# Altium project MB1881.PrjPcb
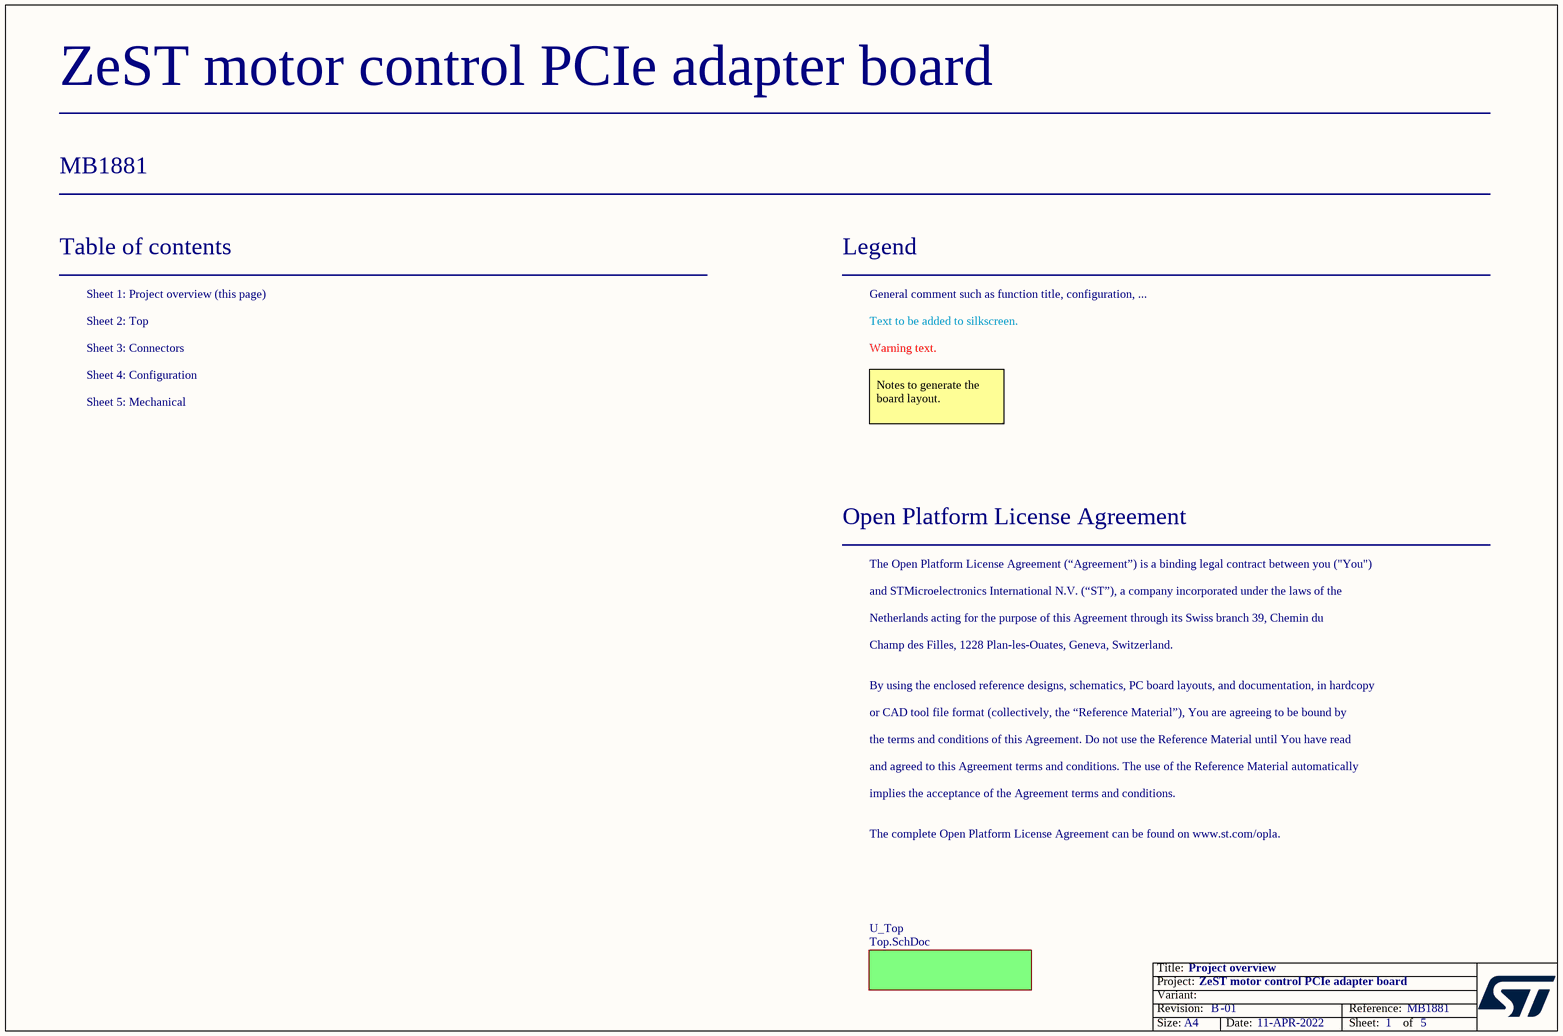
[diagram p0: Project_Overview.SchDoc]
Board_Assembly_Revision: 01; Board_Document_Date: 11-APR-2022; Board_Name: ZeST motor control PCIe adapter board; Board_PCB_Revision: B; Board_Reference: MB1881
5 sheets, 67 parts. Net scope: flat (ports and power ports of the same name join across sheets).
Board file: MB1881.PcbDoc
Sheets:
  Project_Overview.SchDoc
    U_Top = Top.SchDoc
      U_Connectors = Connectors.SchDoc
      U_Configuration = Configuration.SchDoc
      U_Mechanical = Mechanical.SchDoc

## Sheet Project_Overview.SchDoc: Project overview
size A4; Date: Not used; ApprovedBy: Not used; CheckedBy: Not used; Author: Not used; CompanyName: STMicroelectronics; DrawnBy: Not used; Engineer: Not used; Organization: Not used; Address1: Not used; Address2: Not used; Address3: Not used; Address4: Not used; DocumentNumber: Not used; Revision: Not used; SheetNumber: 1; SheetTotal: 5

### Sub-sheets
U_Top = Top.SchDoc: no entries

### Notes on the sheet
- Table of contents
- Sheet 1: Project overview (this page)
- Legend
- General comment such as function title, configuration, ...
- Sheet 2: Top
- Sheet 3: Connectors
- Sheet 4: Configuration
- Text to be added to silkscreen.
- Warning text.
- Sheet 5: Mechanical
- Notes to generate the board layout.
- Open Platform License Agreement
- The Open Platform License Agreement (“Agreement”) is a binding legal contract between you ("You")
- and STMicroelectronics International N.V. (“ST”), a company incorporated under the laws of the
- Netherlands acting for the purpose of this Agreement through its Swiss branch 39, Chemin du
- Champ des Filles, 1228 Plan-les-Ouates, Geneva, Switzerland.
- By using the enclosed reference designs, schematics, PC board layouts, and documentation, in hardcopy
- or CAD tool file format (collectively, the “Reference Material”), You are agreeing to be bound by
- the terms and conditions of this Agreement. Do not use the Reference Material until You have read
- and agreed to this Agreement terms and conditions. The use of the Reference Material automatically
- implies the acceptance of the Agreement terms and conditions.
- The complete Open Platform License Agreement can be found on www.st.com/opla.

## Sheet Top.SchDoc: Top
size A4; Date: Not used; ApprovedBy: Not used; CheckedBy: Not used; Author: Not used; CompanyName: STMicroelectronics; DrawnBy: Not used; Engineer: Not used; Organization: Not used; Address1: Not used; Address2: Not used; Address3: Not used; Address4: Not used; DocumentNumber: Not used; Revision: Not used; SheetNumber: 2; SheetTotal: 5
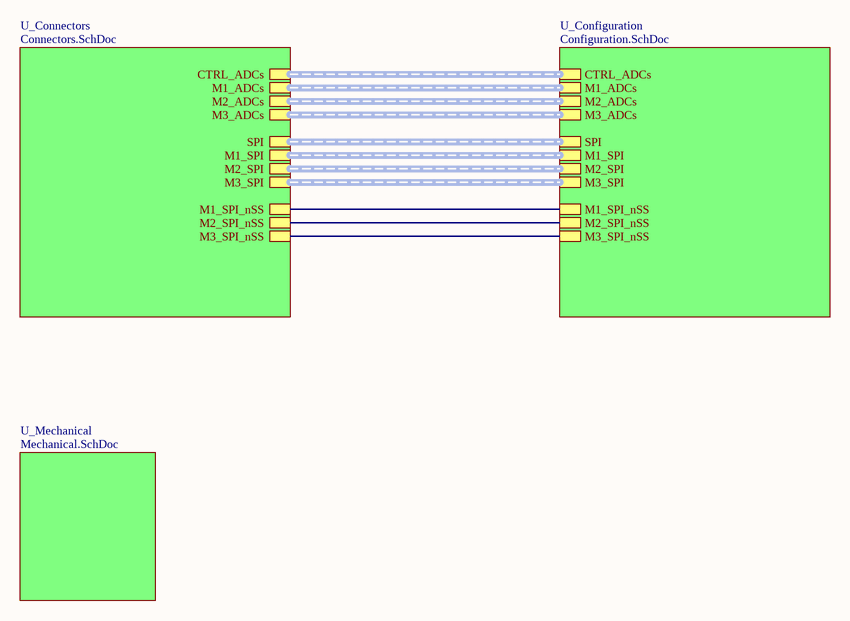
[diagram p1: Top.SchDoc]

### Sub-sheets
U_Configuration = Configuration.SchDoc: CTRL_ADCs (harness ADCs), M1_ADCs (harness ADCs), M3_ADCs (harness ADCs), M2_ADCs (harness ADCs), SPI (harness SPI), M1_SPI (harness SPI), M2_SPI (harness SPI), M3_SPI (harness SPI), M1_SPI_nSS, M3_SPI_nSS, M2_SPI_nSS
U_Connectors = Connectors.SchDoc: M3_ADCs (harness ADCs), CTRL_ADCs (harness ADCs), M1_ADCs (harness ADCs), M2_ADCs (harness ADCs), SPI (harness SPI), M1_SPI (harness SPI), M3_SPI (harness SPI), M2_SPI (harness SPI), M3_SPI_nSS, M1_SPI_nSS, M2_SPI_nSS
U_Mechanical = Mechanical.SchDoc: no entries

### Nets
(unnamed): sheet U_Connectors/M3_SPI_nSS, sheet U_Configuration/M3_SPI_nSS
(unnamed): sheet U_Connectors/M1_SPI_nSS, sheet U_Configuration/M1_SPI_nSS  [a separate net that carries the same name]
(unnamed): sheet U_Connectors/M2_SPI_nSS, sheet U_Configuration/M2_SPI_nSS  [a separate net that carries the same name]

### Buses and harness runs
harness sheet U_Configuration/CTRL_ADCs = sheet U_Connectors/CTRL_ADCs
harness sheet U_Configuration/M1_ADCs = sheet U_Connectors/M1_ADCs
harness sheet U_Configuration/M1_SPI = sheet U_Connectors/M1_SPI
harness sheet U_Configuration/M2_ADCs = sheet U_Connectors/M2_ADCs
harness sheet U_Configuration/M2_SPI = sheet U_Connectors/M2_SPI
harness sheet U_Configuration/M3_ADCs = sheet U_Connectors/M3_ADCs
harness sheet U_Configuration/M3_SPI = sheet U_Connectors/M3_SPI
harness sheet U_Configuration/SPI = sheet U_Connectors/SPI

## Sheet Connectors.SchDoc: Connectors
size A3; Date: Not used; ApprovedBy: Not used; CheckedBy: Not used; Author: Not used; CompanyName: STMicroelectronics; DrawnBy: Not used; Engineer: Not used; Organization: Not used; Address1: Not used; Address2: Not used; Address3: Not used; Address4: Not used; DocumentNumber: Not used; Revision: Not used; SheetNumber: 3; SheetTotal: 5
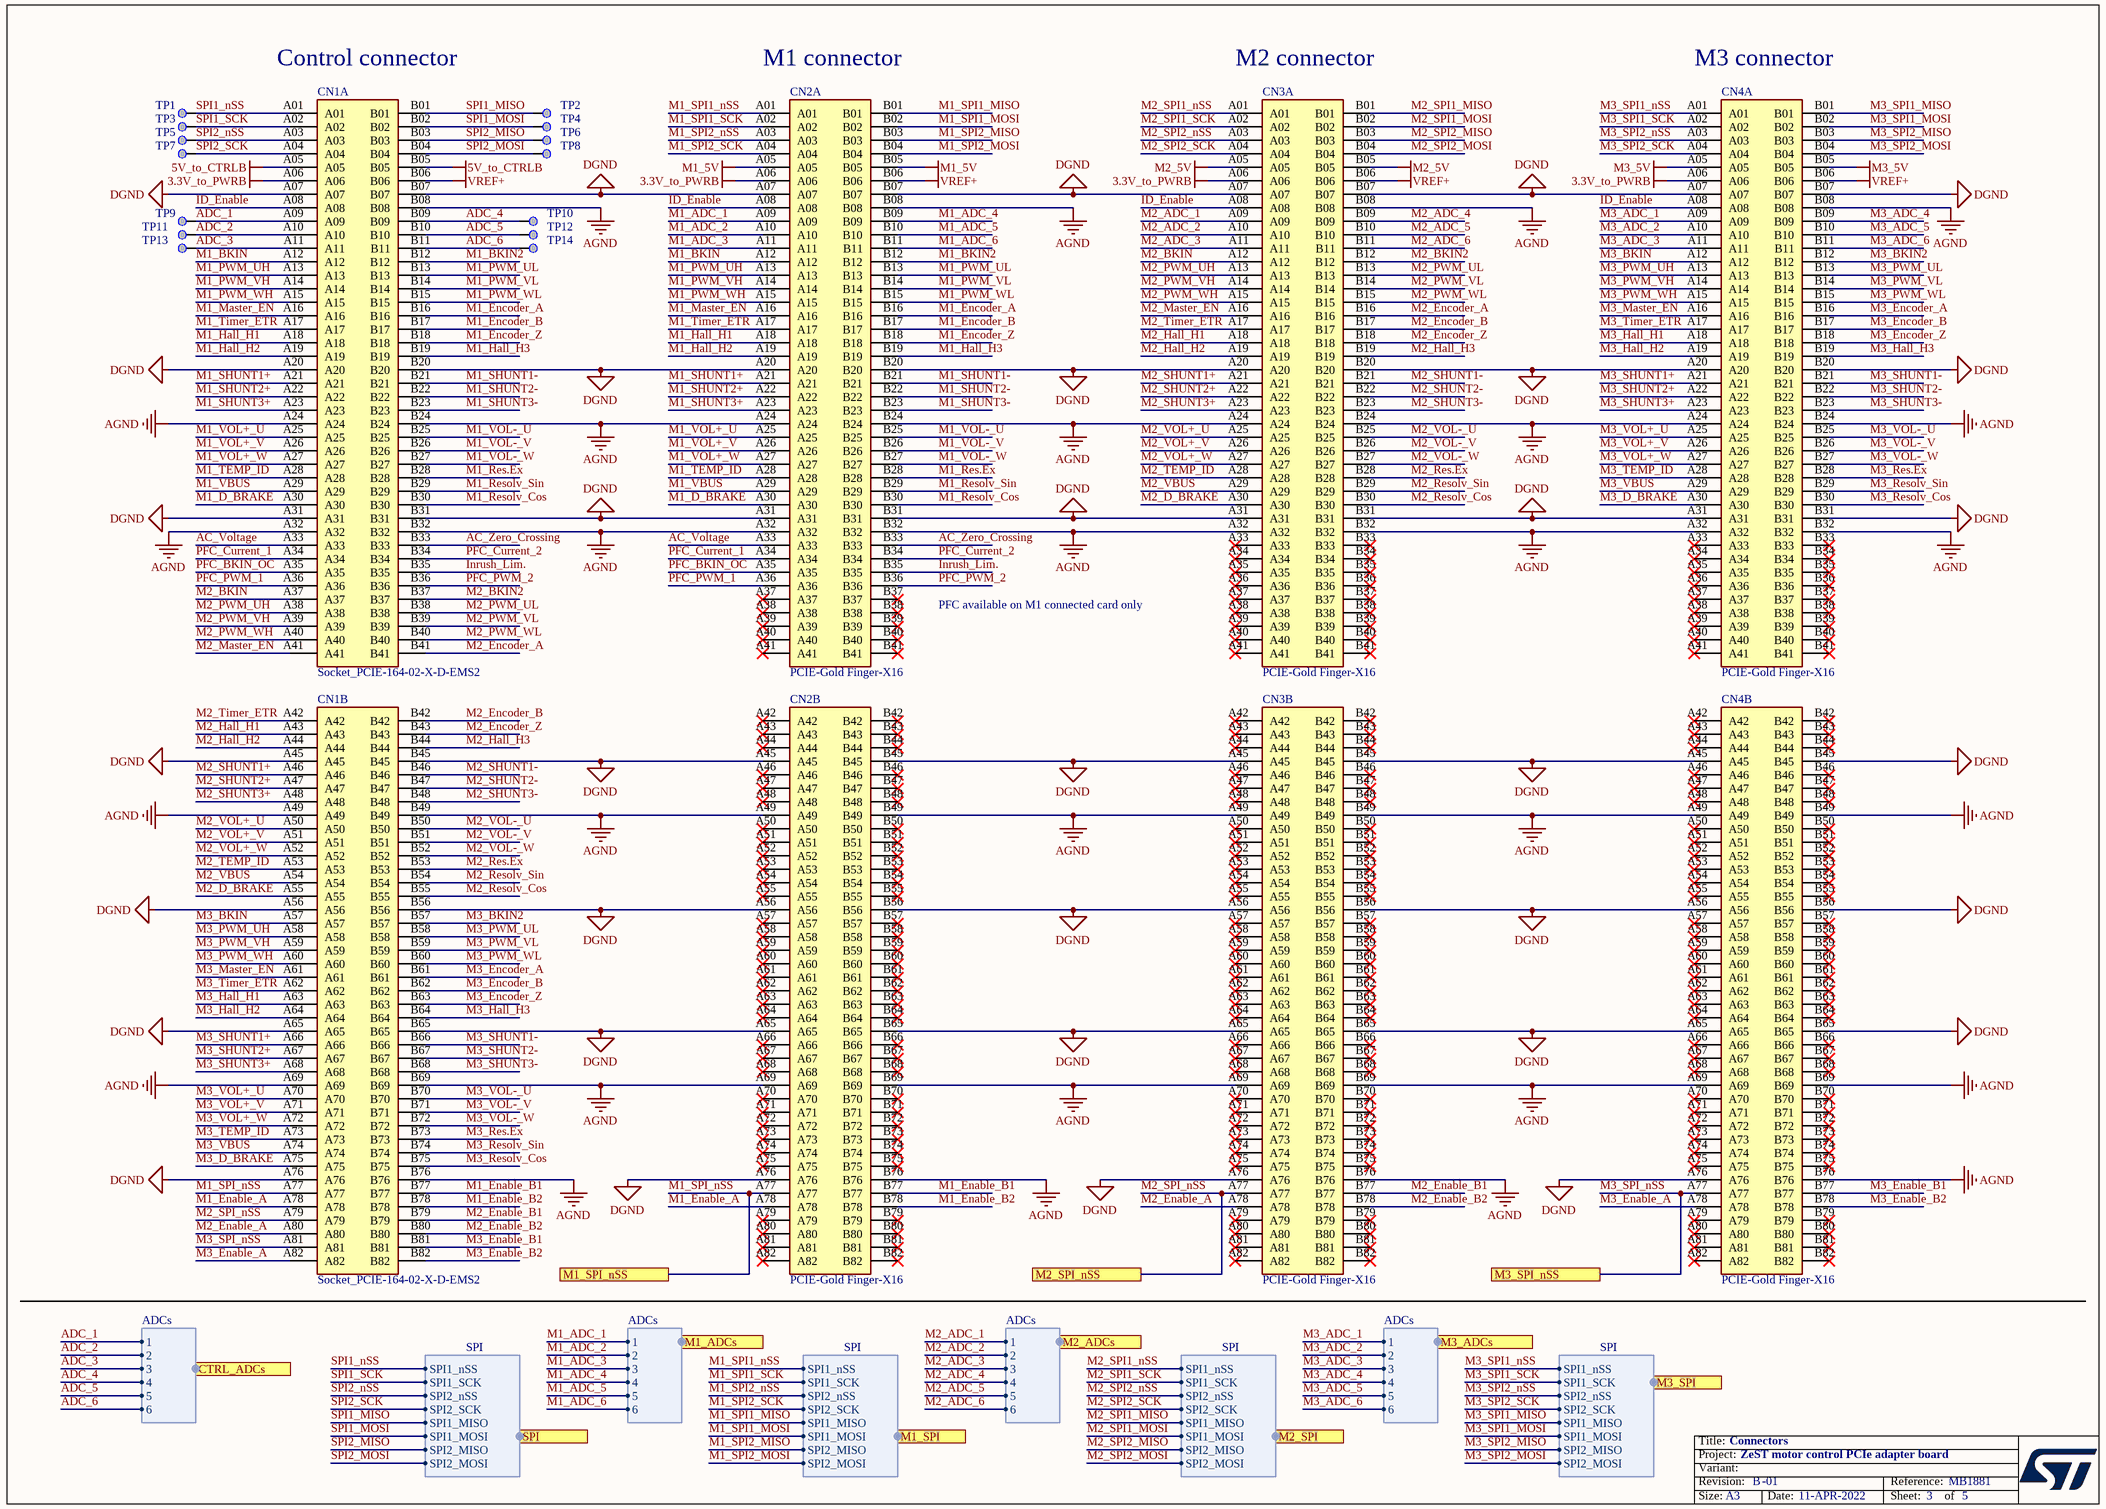
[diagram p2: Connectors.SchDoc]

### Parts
CN1  value Socket_PCIE-164-02-X-D-EMS2  [CON_SAMTEC_PCIE-164-02-X-D-EMS2]  (hidden comment: PCIE-164-02-X-D-EMS2)  (parts A,B of 2)
CN2  PCIE-Gold Finger-X16  [CON_BOARD_GOLDFINGER_PCI_EXPRESS_X16]  (parts A,B of 2)
CN3  PCIE-Gold Finger-X16  [CON_BOARD_GOLDFINGER_PCI_EXPRESS_X16]  (parts A,B of 2)
CN4  PCIE-Gold Finger-X16  [CON_BOARD_GOLDFINGER_PCI_EXPRESS_X16]  (parts A,B of 2)
TP1  Test Point  [TP_SMD_1MM]  (value not drawn)  (no BOM)
TP2  Test Point  [TP_SMD_1MM]  (value not drawn)  (no BOM)
TP3  Test Point  [TP_SMD_1MM]  (value not drawn)  (no BOM)
TP4  Test Point  [TP_SMD_1MM]  (value not drawn)  (no BOM)
TP5  Test Point  [TP_SMD_1MM]  (value not drawn)  (no BOM)
TP6  Test Point  [TP_SMD_1MM]  (value not drawn)  (no BOM)
TP7  Test Point  [TP_SMD_1MM]  (value not drawn)  (no BOM)
TP8  Test Point  [TP_SMD_1MM]  (value not drawn)  (no BOM)
TP9  Test Point  [TP_SMD_1MM]  (value not drawn)  (no BOM)
TP10  Test Point  [TP_SMD_1MM]  (value not drawn)  (no BOM)
TP11  Test Point  [TP_SMD_1MM]  (value not drawn)  (no BOM)
TP12  Test Point  [TP_SMD_1MM]  (value not drawn)  (no BOM)
TP13  Test Point  [TP_SMD_1MM]  (value not drawn)  (no BOM)
TP14  Test Point  [TP_SMD_1MM]  (value not drawn)  (no BOM)

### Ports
CTRL_ADCs (harness ADCs), M1_ADCs (harness ADCs), M1_SPI (harness SPI), M1_SPI_nSS, M2_ADCs (harness ADCs), M2_SPI (harness SPI), M2_SPI_nSS, M3_ADCs (harness ADCs), M3_SPI (harness SPI), M3_SPI_nSS, SPI (harness SPI)

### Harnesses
ADCs: 1, 2, 3, 4, 5, 6
SPI: SPI1_nSS, SPI1_SCK, SPI2_nSS, SPI2_SCK, SPI1_MISO, SPI1_MOSI, SPI2_MISO, SPI2_MOSI

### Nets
3.3V_to_PWRB: CN1.A06 CN2.A06 CN3.A06 CN4.A06
5V_to_CTRLB: CN1.A05 CN1.B05
AGND: CN1.A24 CN1.A32 CN1.A49 CN1.A69 CN1.B08 CN1.B24 CN1.B32 CN1.B49 CN1.B69 CN1.B76 CN2.A24 CN2.A32 CN2.A49 CN2.A69 CN2.B08 CN2.B24 CN2.B32 CN2.B49 CN2.B69 CN2.B76 CN3.A24 CN3.A32 CN3.A49 CN3.A69 CN3.B08 CN3.B24 CN3.B32 CN3.B49 CN3.B69 CN3.B76 CN4.A24 CN4.A32 CN4.A49 CN4.A69 CN4.B08 CN4.B24 CN4.B32 CN4.B49 CN4.B69 CN4.B76
DGND: CN1.A07 CN1.A20 CN1.A31 CN1.A45 CN1.A56 CN1.A65 CN1.A76 CN1.B07 CN1.B20 CN1.B31 CN1.B45 CN1.B56 CN1.B65 CN2.A07 CN2.A20 CN2.A31 CN2.A45 CN2.A56 CN2.A65 CN2.A76 CN2.B07 CN2.B20 CN2.B31 CN2.B45 CN2.B56 CN2.B65 CN3.A07 CN3.A20 CN3.A31 CN3.A45 CN3.A56 CN3.A65 CN3.A76 CN3.B07 CN3.B20 CN3.B31 CN3.B45 CN3.B56 CN3.B65 CN4.A07 CN4.A20 CN4.A31 CN4.A45 CN4.A56 CN4.A65 CN4.A76 CN4.B07 CN4.B20 CN4.B31 CN4.B45 CN4.B56 CN4.B65
M1_5V: CN2.A05 CN2.B05
M2_5V: CN3.A05 CN3.B05
M3_5V: CN4.A05 CN4.B05
VREF+: CN1.B06 CN2.B06 CN3.B06 CN4.B06
AC_Voltage: CN1.A33 CN2.A33
AC_Zero_Crossing: CN1.B33 CN2.B33
ADC_1: CN1.A09 TP9.1 ; port CTRL_ADCs.1
ADC_2: CN1.A10 TP11.1 ; port CTRL_ADCs.2
ADC_3: CN1.A11 TP13.1 ; port CTRL_ADCs.3
ADC_4: CN1.B09 TP10.1 ; port CTRL_ADCs.4
ADC_5: CN1.B10 TP12.1 ; port CTRL_ADCs.5
ADC_6: CN1.B11 TP14.1 ; port CTRL_ADCs.6
ID_Enable: CN1.A08 CN2.A08 CN3.A08 CN4.A08
Inrush_Lim.: CN1.B35 CN2.B35
M1_ADC_1: CN2.A09 ; port M1_ADCs.1
M1_ADC_2: CN2.A10 ; port M1_ADCs.2
M1_ADC_3: CN2.A11 ; port M1_ADCs.3
M1_ADC_4: CN2.B09 ; port M1_ADCs.4
M1_ADC_5: CN2.B10 ; port M1_ADCs.5
M1_ADC_6: CN2.B11 ; port M1_ADCs.6
M1_BKIN: CN1.A12 CN2.A12
M1_BKIN2: CN1.B12 CN2.B12
M1_D_BRAKE: CN1.A30 CN2.A30
M1_Enable_A: CN1.A78 CN2.A78
M1_Enable_B1: CN1.B77 CN2.B77
M1_Enable_B2: CN1.B78 CN2.B78
M1_Encoder_A: CN1.B16 CN2.B16
M1_Encoder_B: CN1.B17 CN2.B17
M1_Encoder_Z: CN1.B18 CN2.B18
M1_Hall_H1: CN1.A18 CN2.A18
M1_Hall_H2: CN1.A19 CN2.A19
M1_Hall_H3: CN1.B19 CN2.B19
M1_Master_EN: CN1.A16 CN2.A16
M1_PWM_UH: CN1.A13 CN2.A13
M1_PWM_UL: CN1.B13 CN2.B13
M1_PWM_VH: CN1.A14 CN2.A14
M1_PWM_VL: CN1.B14 CN2.B14
M1_PWM_WH: CN1.A15 CN2.A15
M1_PWM_WL: CN1.B15 CN2.B15
M1_Res.Ex: CN1.B28 CN2.B28
M1_Resolv_Cos: CN1.B30 CN2.B30
M1_Resolv_Sin: CN1.B29 CN2.B29
M1_SHUNT1+: CN1.A21 CN2.A21
M1_SHUNT1-: CN1.B21 CN2.B21
M1_SHUNT2+: CN1.A22 CN2.A22
M1_SHUNT2-: CN1.B22 CN2.B22
M1_SHUNT3+: CN1.A23 CN2.A23
M1_SHUNT3-: CN1.B23 CN2.B23
M1_SPI1_MISO: CN2.B01 ; port M1_SPI.SPI1_MISO
M1_SPI1_MOSI: CN1.B02 CN2.B02 CN3.B02 CN4.B02 TP4.1 ; port SPI.SPI1_MOSI, port M1_SPI.SPI1_MOSI, port M2_SPI.SPI1_MOSI, port M3_SPI.SPI1_MOSI  [also labelled M2_SPI1_MOSI, M3_SPI1_MOSI, SPI1_MOSI]
M1_SPI1_nSS: CN2.A01 ; port M1_SPI.SPI1_nSS
M1_SPI1_SCK: CN1.A02 CN2.A02 CN3.A02 CN4.A02 TP3.1 ; port SPI.SPI1_SCK, port M1_SPI.SPI1_SCK, port M2_SPI.SPI1_SCK, port M3_SPI.SPI1_SCK  [also labelled M2_SPI1_SCK, M3_SPI1_SCK, SPI1_SCK]
M1_SPI2_MISO: CN2.B03 ; port M1_SPI.SPI2_MISO
M1_SPI2_MOSI: CN1.B04 CN2.B04 CN3.B04 CN4.B04 TP8.1 ; port SPI.SPI2_MOSI, port M1_SPI.SPI2_MOSI, port M2_SPI.SPI2_MOSI, port M3_SPI.SPI2_MOSI  [also labelled M2_SPI2_MOSI, M3_SPI2_MOSI, SPI2_MOSI]
M1_SPI2_nSS: CN2.A03 ; port M1_SPI.SPI2_nSS
M1_SPI2_SCK: CN1.A04 CN2.A04 CN3.A04 CN4.A04 TP7.1 ; port SPI.SPI2_SCK, port M1_SPI.SPI2_SCK, port M2_SPI.SPI2_SCK, port M3_SPI.SPI2_SCK  [also labelled M2_SPI2_SCK, M3_SPI2_SCK, SPI2_SCK]
M1_SPI_nSS: CN1.A77 CN2.A77 ; port M1_SPI_nSS
M1_TEMP_ID: CN1.A28 CN2.A28
M1_Timer_ETR: CN1.A17 CN2.A17
M1_VBUS: CN1.A29 CN2.A29
M1_VOL+_U: CN1.A25 CN2.A25
M1_VOL+_V: CN1.A26 CN2.A26
M1_VOL+_W: CN1.A27 CN2.A27
M1_VOL-_U: CN1.B25 CN2.B25
M1_VOL-_V: CN1.B26 CN2.B26
M1_VOL-_W: CN1.B27 CN2.B27
M2_ADC_1: CN3.A09 ; port M2_ADCs.1
M2_ADC_2: CN3.A10 ; port M2_ADCs.2
M2_ADC_3: CN3.A11 ; port M2_ADCs.3
M2_ADC_4: CN3.B09 ; port M2_ADCs.4
M2_ADC_5: CN3.B10 ; port M2_ADCs.5
M2_ADC_6: CN3.B11 ; port M2_ADCs.6
M2_BKIN: CN1.A37 CN3.A12
M2_BKIN2: CN1.B37 CN3.B12
M2_D_BRAKE: CN1.A55 CN3.A30
M2_Enable_A: CN1.A80 CN3.A78
M2_Enable_B1: CN1.B79 CN3.B77
M2_Enable_B2: CN1.B80 CN3.B78
M2_Encoder_A: CN1.B41 CN3.B16
M2_Encoder_B: CN1.B42 CN3.B17
M2_Encoder_Z: CN1.B43 CN3.B18
M2_Hall_H1: CN1.A43 CN3.A18
M2_Hall_H2: CN1.A44 CN3.A19
M2_Hall_H3: CN1.B44 CN3.B19
M2_Master_EN: CN1.A41 CN3.A16
M2_PWM_UH: CN1.A38 CN3.A13
M2_PWM_UL: CN1.B38 CN3.B13
M2_PWM_VH: CN1.A39 CN3.A14
M2_PWM_VL: CN1.B39 CN3.B14
M2_PWM_WH: CN1.A40 CN3.A15
M2_PWM_WL: CN1.B40 CN3.B15
M2_Res.Ex: CN1.B53 CN3.B28
M2_Resolv_Cos: CN1.B55 CN3.B30
M2_Resolv_Sin: CN1.B54 CN3.B29
M2_SHUNT1+: CN1.A46 CN3.A21
M2_SHUNT1-: CN1.B46 CN3.B21
M2_SHUNT2+: CN1.A47 CN3.A22
M2_SHUNT2-: CN1.B47 CN3.B22
M2_SHUNT3+: CN1.A48 CN3.A23
M2_SHUNT3-: CN1.B48 CN3.B23
M2_SPI1_MISO: CN3.B01 ; port M2_SPI.SPI1_MISO
M2_SPI1_nSS: CN3.A01 ; port M2_SPI.SPI1_nSS
M2_SPI2_MISO: CN3.B03 ; port M2_SPI.SPI2_MISO
M2_SPI2_nSS: CN3.A03 ; port M2_SPI.SPI2_nSS
M2_SPI_nSS: CN1.A79 CN3.A77 ; port M2_SPI_nSS
M2_TEMP_ID: CN1.A53 CN3.A28
M2_Timer_ETR: CN1.A42 CN3.A17
M2_VBUS: CN1.A54 CN3.A29
M2_VOL+_U: CN1.A50 CN3.A25
M2_VOL+_V: CN1.A51 CN3.A26
M2_VOL+_W: CN1.A52 CN3.A27
M2_VOL-_U: CN1.B50 CN3.B25
M2_VOL-_V: CN1.B51 CN3.B26
M2_VOL-_W: CN1.B52 CN3.B27
M3_ADC_1: CN4.A09 ; port M3_ADCs.1
M3_ADC_2: CN4.A10 ; port M3_ADCs.2
M3_ADC_3: CN4.A11 ; port M3_ADCs.3
M3_ADC_4: CN4.B09 ; port M3_ADCs.4
M3_ADC_5: CN4.B10 ; port M3_ADCs.5
M3_ADC_6: CN4.B11 ; port M3_ADCs.6
M3_BKIN: CN1.A57 CN4.A12
M3_BKIN2: CN1.B57 CN4.B12
M3_D_BRAKE: CN1.A75 CN4.A30
M3_Enable_A: CN1.A82 CN4.A78
M3_Enable_B1: CN1.B81 CN4.B77
M3_Enable_B2: CN1.B82 CN4.B78
M3_Encoder_A: CN1.B61 CN4.B16
M3_Encoder_B: CN1.B62 CN4.B17
M3_Encoder_Z: CN1.B63 CN4.B18
M3_Hall_H1: CN1.A63 CN4.A18
M3_Hall_H2: CN1.A64 CN4.A19
M3_Hall_H3: CN1.B64 CN4.B19
M3_Master_EN: CN1.A61 CN4.A16
M3_PWM_UH: CN1.A58 CN4.A13
M3_PWM_UL: CN1.B58 CN4.B13
M3_PWM_VH: CN1.A59 CN4.A14
M3_PWM_VL: CN1.B59 CN4.B14
M3_PWM_WH: CN1.A60 CN4.A15
M3_PWM_WL: CN1.B60 CN4.B15
M3_Res.Ex: CN1.B73 CN4.B28
M3_Resolv_Cos: CN1.B75 CN4.B30
M3_Resolv_Sin: CN1.B74 CN4.B29
M3_SHUNT1+: CN1.A66 CN4.A21
M3_SHUNT1-: CN1.B66 CN4.B21
M3_SHUNT2+: CN1.A67 CN4.A22
M3_SHUNT2-: CN1.B67 CN4.B22
M3_SHUNT3+: CN1.A68 CN4.A23
M3_SHUNT3-: CN1.B68 CN4.B23
M3_SPI1_MISO: CN4.B01 ; port M3_SPI.SPI1_MISO
M3_SPI1_nSS: CN4.A01 ; port M3_SPI.SPI1_nSS
M3_SPI2_MISO: CN4.B03 ; port M3_SPI.SPI2_MISO
M3_SPI2_nSS: CN4.A03 ; port M3_SPI.SPI2_nSS
M3_SPI_nSS: CN1.A81 CN4.A77 ; port M3_SPI_nSS
M3_TEMP_ID: CN1.A73 CN4.A28
M3_Timer_ETR: CN1.A62 CN4.A17
M3_VBUS: CN1.A74 CN4.A29
M3_VOL+_U: CN1.A70 CN4.A25
M3_VOL+_V: CN1.A71 CN4.A26
M3_VOL+_W: CN1.A72 CN4.A27
M3_VOL-_U: CN1.B70 CN4.B25
M3_VOL-_V: CN1.B71 CN4.B26
M3_VOL-_W: CN1.B72 CN4.B27
PFC_BKIN_OC: CN1.A35 CN2.A35
PFC_Current_1: CN1.A34 CN2.A34
PFC_Current_2: CN1.B34 CN2.B34
PFC_PWM_1: CN1.A36 CN2.A36
PFC_PWM_2: CN1.B36 CN2.B36
SPI1_MISO: CN1.B01 TP2.1 ; port SPI.SPI1_MISO
SPI1_nSS: CN1.A01 TP1.1 ; port SPI.SPI1_nSS
SPI2_MISO: CN1.B03 TP6.1 ; port SPI.SPI2_MISO
SPI2_nSS: CN1.A03 TP5.1 ; port SPI.SPI2_nSS

Not connected (* = marked no-connect by the designer): CN2 A37* A38* A39* A40* A41* A42* A43* A44* A46* A47* A48* A50* A51* A52* A53* A54* A55* A57* A58* A59* A60* A61* A62* A63* A64* A66* A67* A68* A70* A71* A72* A73* A74* A75* A79* A80* A81* A82* B37* B38* B39* B40* B41* B42* B43* B44* B46* B47* B48* B50* B51* B52* B53* B54* B55* B57* B58* B59* B60* B61* B62* B63* B64* B66* B67* B68* B70* B71* B72* B73* B74* B75* B79* B80* B81* B82*; CN3 A33* A34* A35* A36* A37* A38* A39* A40* A41* A42* A43* A44* A46* A47* A48* A50* A51* A52* A53* A54* A55* A57* A58* A59* A60* A61* A62* A63* A64* A66* A67* A68* A70* A71* A72* A73* A74* A75* A79* A80* A81* A82* B33* B34* B35* B36* B37* B38* B39* B40* B41* B42* B43* B44* B46* B47* B48* B50* B51* B52* B53* B54* B55* B57* B58* B59* B60* B61* B62* B63* B64* B66* B67* B68* B70* B71* B72* B73* B74* B75* B79* B80* B81* B82*; CN4 A33* A34* A35* A36* A37* A38* A39* A40* A41* A42* A43* A44* A46* A47* A48* A50* A51* A52* A53* A54* A55* A57* A58* A59* A60* A61* A62* A63* A64* A66* A67* A68* A70* A71* A72* A73* A74* A75* A79* A80* A81* A82* B33* B34* B35* B36* B37* B38* B39* B40* B41* B42* B43* B44* B46* B47* B48* B50* B51* B52* B53* B54* B55* B57* B58* B59* B60* B61* B62* B63* B64* B66* B67* B68* B70* B71* B72* B73* B74* B75* B79* B80* B81* B82*

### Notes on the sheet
- (near CN1) Control connector
- (near CN2) M1 connector
- (near CN3) M2 connector
- (near CN4) M3 connector
- PFC available on M1 connected card only

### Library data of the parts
CN1 = MCD-02913: 1.00 mm PCI Express Edge Card Connector; Part_Preference: Recommended; Manufacturer: SAMTEC; Component_Country_Of_Origin: USA°; ShowFields: YES; ID: 5029
CN2-CN4 = MCD-02436: PCI EXPRESS x16 Add-in Card Edge-Finger; Part_Type: Mechanical; Part_Preference: Recommended
TP1-TP14 = MCD-00074: Test Point 1mm; Part_Type: Misc; Part_Preference: Recommended

## Sheet Configuration.SchDoc: Configuration
size A4; Date: Not used; ApprovedBy: Not used; CheckedBy: Not used; Author: Not used; CompanyName: STMicroelectronics; DrawnBy: Not used; Engineer: Not used; Organization: Not used; Address1: Not used; Address2: Not used; Address3: Not used; Address4: Not used; DocumentNumber: Not used; Revision: Not used; SheetNumber: 4; SheetTotal: 5
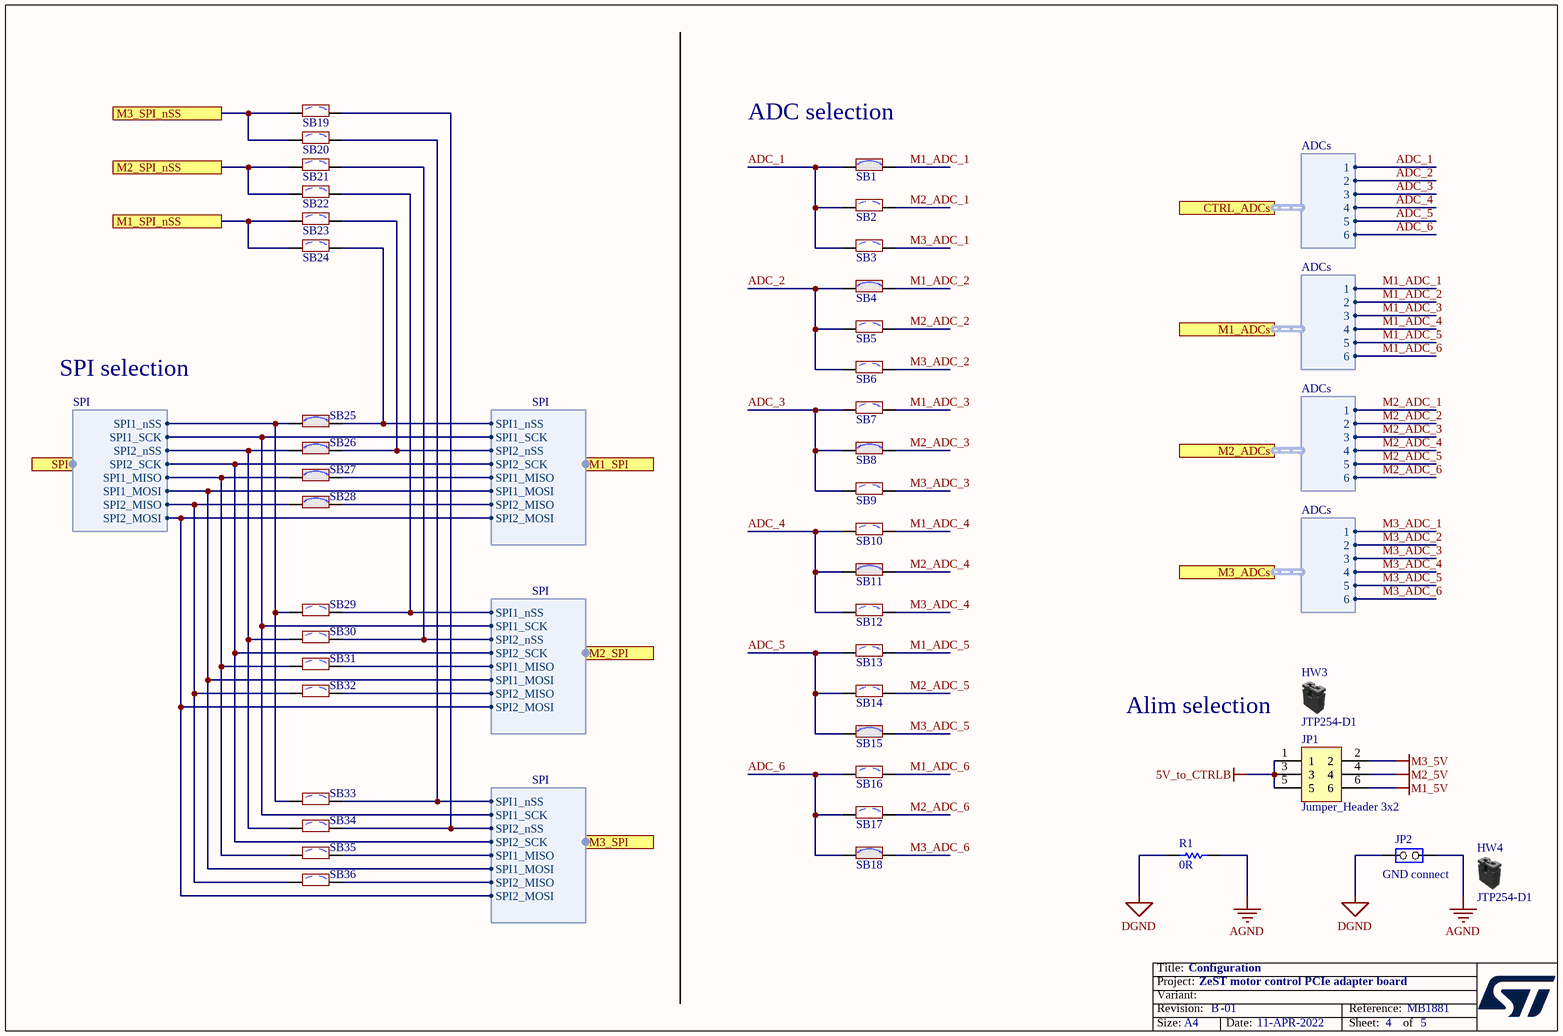
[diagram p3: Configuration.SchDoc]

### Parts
HW3  value JTP254-D1  (hidden comment: Shunt Black 2.54mm)  (mechanical)
HW4  value JTP254-D1  (hidden comment: Shunt Black 2.54mm)  (mechanical)
JP1  value Jumper_Header 3x2  [CON_SAMTEC_TSW-103-07-X-D]  (hidden comment: Header 3x2)
JP2  value GND connect  [CON_SAMTEC_TSW-102-07-G-S]  (hidden comment: Jumper_Header 2x1)
R1  value 0R  [R1206_H0P55]  (hidden comment: Resistor)
SB1  SB_ON  [SOLDER-BRIDGE_R0402-0R]  (value not drawn)
SB2  SB_OFF  [SOLDER-BRIDGE_R0402-0R]  (value not drawn)
SB3  SB_OFF  [SOLDER-BRIDGE_R0402-0R]  (value not drawn)
SB4  SB_ON  [SOLDER-BRIDGE_R0402-0R]  (value not drawn)
SB5  SB_OFF  [SOLDER-BRIDGE_R0402-0R]  (value not drawn)
SB6  SB_OFF  [SOLDER-BRIDGE_R0402-0R]  (value not drawn)
SB7  SB_OFF  [SOLDER-BRIDGE_R0402-0R]  (value not drawn)
SB8  SB_ON  [SOLDER-BRIDGE_R0402-0R]  (value not drawn)
SB9  SB_OFF  [SOLDER-BRIDGE_R0402-0R]  (value not drawn)
SB10  SB_OFF  [SOLDER-BRIDGE_R0402-0R]  (value not drawn)
SB11  SB_ON  [SOLDER-BRIDGE_R0402-0R]  (value not drawn)
SB12  SB_OFF  [SOLDER-BRIDGE_R0402-0R]  (value not drawn)
SB13  SB_OFF  [SOLDER-BRIDGE_R0402-0R]  (value not drawn)
SB14  SB_OFF  [SOLDER-BRIDGE_R0402-0R]  (value not drawn)
SB15  SB_ON  [SOLDER-BRIDGE_R0402-0R]  (value not drawn)
SB16  SB_OFF  [SOLDER-BRIDGE_R0402-0R]  (value not drawn)
SB17  SB_OFF  [SOLDER-BRIDGE_R0402-0R]  (value not drawn)
SB18  SB_ON  [SOLDER-BRIDGE_R0402-0R]  (value not drawn)
SB19  SB_OFF  [SOLDER-BRIDGE_R0402-0R]  (value not drawn)
SB20  SB_OFF  [SOLDER-BRIDGE_R0402-0R]  (value not drawn)
SB21  SB_OFF  [SOLDER-BRIDGE_R0402-0R]  (value not drawn)
SB22  SB_OFF  [SOLDER-BRIDGE_R0402-0R]  (value not drawn)
SB23  SB_OFF  [SOLDER-BRIDGE_R0402-0R]  (value not drawn)
SB24  SB_OFF  [SOLDER-BRIDGE_R0402-0R]  (value not drawn)
SB25  SB_ON  [SOLDER-BRIDGE_R0402-0R]  (value not drawn)
SB26  SB_ON  [SOLDER-BRIDGE_R0402-0R]  (value not drawn)
SB27  SB_ON  [SOLDER-BRIDGE_R0402-0R]  (value not drawn)
SB28  SB_ON  [SOLDER-BRIDGE_R0402-0R]  (value not drawn)
SB29  SB_OFF  [SOLDER-BRIDGE_R0402-0R]  (value not drawn)
SB30  SB_OFF  [SOLDER-BRIDGE_R0402-0R]  (value not drawn)
SB31  SB_OFF  [SOLDER-BRIDGE_R0402-0R]  (value not drawn)
SB32  SB_OFF  [SOLDER-BRIDGE_R0402-0R]  (value not drawn)
SB33  SB_OFF  [SOLDER-BRIDGE_R0402-0R]  (value not drawn)
SB34  SB_OFF  [SOLDER-BRIDGE_R0402-0R]  (value not drawn)
SB35  SB_OFF  [SOLDER-BRIDGE_R0402-0R]  (value not drawn)
SB36  SB_OFF  [SOLDER-BRIDGE_R0402-0R]  (value not drawn)

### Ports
CTRL_ADCs (harness ADCs), M1_ADCs (harness ADCs), M1_SPI (harness SPI), M1_SPI_nSS, M2_ADCs (harness ADCs), M2_SPI (harness SPI), M2_SPI_nSS, M3_ADCs (harness ADCs), M3_SPI (harness SPI), M3_SPI_nSS, SPI (harness SPI)

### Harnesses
ADCs: 1, 2, 3, 4, 5, 6
SPI: SPI1_nSS, SPI1_SCK, SPI2_nSS, SPI2_SCK, SPI1_MISO, SPI1_MOSI, SPI2_MISO, SPI2_MOSI

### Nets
5V_to_CTRLB: JP1.1 JP1.3 JP1.5
AGND: JP2.2(NO) R1.2
DGND: JP2.1(COMMON) R1.1
M1_5V: JP1.6
M2_5V: JP1.4
M3_5V: JP1.2
ADC_1: SB1.1 SB2.1 SB3.1 ; port CTRL_ADCs.1
ADC_2: SB4.1 SB5.1 SB6.1 ; port CTRL_ADCs.2
ADC_3: SB7.1 SB8.1 SB9.1 ; port CTRL_ADCs.3
ADC_4: SB10.1 SB11.1 SB12.1 ; port CTRL_ADCs.4
ADC_5: SB13.1 SB14.1 SB15.1 ; port CTRL_ADCs.5
ADC_6: SB16.1 SB17.1 SB18.1 ; port CTRL_ADCs.6
M1_ADC_1: SB1.2 ; port M1_ADCs.1
M1_ADC_2: SB4.2 ; port M1_ADCs.2
M1_ADC_3: SB7.2 ; port M1_ADCs.3
M1_ADC_4: SB10.2 ; port M1_ADCs.4
M1_ADC_5: SB13.2 ; port M1_ADCs.5
M1_ADC_6: SB16.2 ; port M1_ADCs.6
M1_SPI1_MISO: SB27.2 ; port M1_SPI.SPI1_MISO
M1_SPI1_MOSI: port SPI.SPI1_MOSI, port M1_SPI.SPI1_MOSI, port M2_SPI.SPI1_MOSI, port M3_SPI.SPI1_MOSI
M1_SPI1_nSS: SB24.2 SB25.2 ; port M1_SPI.SPI1_nSS
M1_SPI1_SCK: port SPI.SPI1_SCK, port M1_SPI.SPI1_SCK, port M2_SPI.SPI1_SCK, port M3_SPI.SPI1_SCK
M1_SPI2_MISO: SB28.2 ; port M1_SPI.SPI2_MISO
M1_SPI2_MOSI: port SPI.SPI2_MOSI, port M1_SPI.SPI2_MOSI, port M2_SPI.SPI2_MOSI, port M3_SPI.SPI2_MOSI
M1_SPI2_nSS: SB23.2 SB26.2 ; port M1_SPI.SPI2_nSS
M1_SPI2_SCK: port SPI.SPI2_SCK, port M1_SPI.SPI2_SCK, port M2_SPI.SPI2_SCK, port M3_SPI.SPI2_SCK
M1_SPI_nSS: SB23.1 SB24.1 ; port M1_SPI_nSS
M2_ADC_1: SB2.2 ; port M2_ADCs.1
M2_ADC_2: SB5.2 ; port M2_ADCs.2
M2_ADC_3: SB8.2 ; port M2_ADCs.3
M2_ADC_4: SB11.2 ; port M2_ADCs.4
M2_ADC_5: SB14.2 ; port M2_ADCs.5
M2_ADC_6: SB17.2 ; port M2_ADCs.6
M2_SPI1_MISO: SB31.2 ; port M2_SPI.SPI1_MISO
M2_SPI1_nSS: SB22.2 SB29.2 ; port M2_SPI.SPI1_nSS
M2_SPI2_MISO: SB32.2 ; port M2_SPI.SPI2_MISO
M2_SPI2_nSS: SB21.2 SB30.2 ; port M2_SPI.SPI2_nSS
M2_SPI_nSS: SB21.1 SB22.1 ; port M2_SPI_nSS
M3_ADC_1: SB3.2 ; port M3_ADCs.1
M3_ADC_2: SB6.2 ; port M3_ADCs.2
M3_ADC_3: SB9.2 ; port M3_ADCs.3
M3_ADC_4: SB12.2 ; port M3_ADCs.4
M3_ADC_5: SB15.2 ; port M3_ADCs.5
M3_ADC_6: SB18.2 ; port M3_ADCs.6
M3_SPI1_MISO: SB35.2 ; port M3_SPI.SPI1_MISO
M3_SPI1_nSS: SB20.2 SB33.2 ; port M3_SPI.SPI1_nSS
M3_SPI2_MISO: SB36.2 ; port M3_SPI.SPI2_MISO
M3_SPI2_nSS: SB19.2 SB34.2 ; port M3_SPI.SPI2_nSS
M3_SPI_nSS: SB19.1 SB20.1 ; port M3_SPI_nSS
SPI1_MISO: SB27.1 SB31.1 SB35.1 ; port SPI.SPI1_MISO
SPI1_nSS: SB25.1 SB29.1 SB33.1 ; port SPI.SPI1_nSS
SPI2_MISO: SB28.1 SB32.1 SB36.1 ; port SPI.SPI2_MISO
SPI2_nSS: SB26.1 SB30.1 SB34.1 ; port SPI.SPI2_nSS

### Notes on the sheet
- (near SB1) ADC selection
- SPI selection
- (near HW3) Alim selection

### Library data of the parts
HW3 HW4 = MCD-02388: SHUNT 2.54mm BLACK; Part_Type: Misc; Part_Preference: Not recommended; Manufacturer: MTCONN
JP1 = MCD-00233: Header, 3x2, 2.54mm, VR, TH, T=5.84mm/2.54mm; Part_Type: Connector; Part_Preference: Recommended; Manufacturer: SAMTEC; Manufacturer_Part_Number: TSW-103-07-G-D; Order_Code_RS: 161-2249; Component_Country_Of_Origin: China, Costa Rica, Malaysia, United States, Vietnam
JP2 = MCD-02390: Header, 2x1, 2,54mm, VR, TH, T=6mm/3mm; Part_Type: Connector; Part_Preference: Not recommended; Manufacturer: MTCONN; Manufacturer_Part_Number: JT254-D180-102-001
R1 = MCD-00180: Resistor, 0R, 1206, +/-5%, 1/4W; Part_Preference: Recommended; Manufacturer: YAGEO; Manufacturer_Part_Number: RC1206JR-070RL; Component_Country_Of_Origin: China
SB1 SB4 SB8 SB11 SB15 SB18 SB25-SB28 = MCD-01618: Solder Bridge 0402 ON; Part_Type: Misc; Part_Preference: Recommended; Manufacturer: YAGEO; Manufacturer_Part_Number: RC0402JR-070RL; Order_Code_RS: 618-5804; Component_Country_Of_Origin: China
SB2 SB3 SB5-SB7 SB9 SB10 SB12-SB14 SB16 SB17 SB19-SB24 SB29-SB36 = MCD-02162: Solder Bridge 0402 OFF; Part_Type: Misc; Part_Preference: Recommended; Manufacturer: YAGEO; Manufacturer_Part_Number: RC0402JR-070RL; Order_Code_RS: 618-5804; Component_Country_Of_Origin: China

## Sheet Mechanical.SchDoc: Mechanical
size A4; Date: Not used; ApprovedBy: Not used; CheckedBy: Not used; Author: Not used; CompanyName: STMicroelectronics; DrawnBy: Not used; Engineer: Not used; Organization: Not used; Address1: Not used; Address2: Not used; Address3: Not used; Address4: Not used; DocumentNumber: Not used; Revision: Not used; SheetNumber: 5; SheetTotal: 5
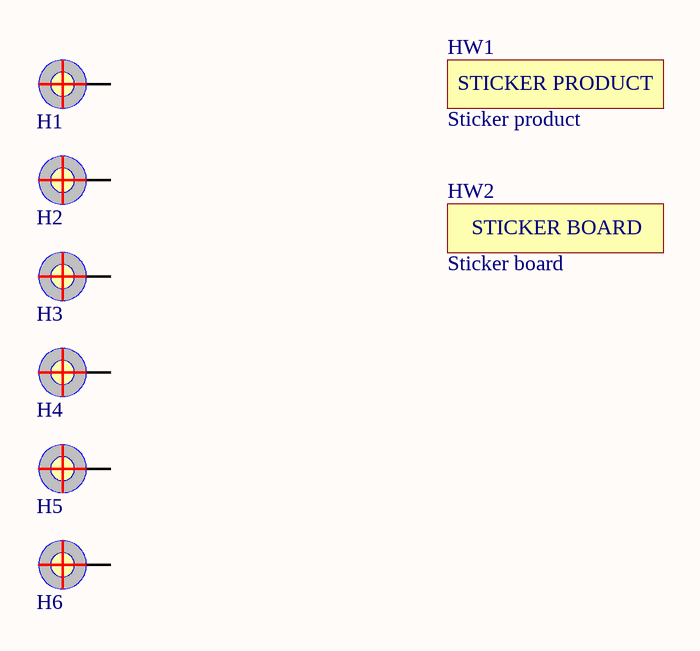
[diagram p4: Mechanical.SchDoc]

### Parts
H1  POSITION HOLE  [PTH_M1261-3005-N_3P5X6_M3_H14]  (value not drawn)  (no BOM)
H2  POSITION HOLE  [PTH_M1261-3005-N_3P5X6_M3_H14]  (value not drawn)  (no BOM)
H3  POSITION HOLE  [PTH_M1261-3005-N_3P5X6_M3_H14]  (value not drawn)  (no BOM)
H4  POSITION HOLE  [PTH_M1261-3005-N_3P5X6_M3_H14]  (value not drawn)  (no BOM)
H5  POSITION HOLE  [PTH_M1261-3005-N_3P5X6_M3_H14]  (value not drawn)  (no BOM)
H6  POSITION HOLE  [PTH_M1261-3005-N_3P5X6_M3_H14]  (value not drawn)  (no BOM)
HW1  value Sticker product  [STICKER_PRODUCT_25X9]  (hidden comment: STICKER_PRODUCT)  (no BOM)
HW2  value Sticker board  [STICKER_BOARD_25X9]  (hidden comment: MB1181)  (no BOM)

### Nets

Not connected (* = marked no-connect by the designer): H1 1; H2 1; H3 1; H4 1; H5 1; H6 1

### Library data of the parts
H1-H6 = MCD-00035: POSITION HOLE C6D3R5; Part_Type: Misc; Part_Preference: Recommended
HW1 = MCD-00547: Sticker product 25x9 mm; Part_Type: Misc; Part_Preference: Recommended
HW2 = MCD-00235: Sticker Board 25x9 mm; Part_Type: Misc; Part_Preference: Recommended

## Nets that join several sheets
5V_to_CTRLB: Connectors (CN1.A05 CN1.B05), Configuration (JP1.1 JP1.3 JP1.5)
AGND: Connectors (40 pins), Configuration (JP2.2 R1.2)
DGND: Connectors (52 pins), Configuration (JP2.1 R1.1)
M1_5V: Connectors (CN2.A05 CN2.B05), Configuration (JP1.6)
M2_5V: Connectors (CN3.A05 CN3.B05), Configuration (JP1.4)
M3_5V: Connectors (CN4.A05 CN4.B05), Configuration (JP1.2)
ADC_1: Connectors (CN1.A09 TP9.1), Configuration (SB1.1 SB2.1 SB3.1)
ADC_2: Connectors (CN1.A10 TP11.1), Configuration (SB4.1 SB5.1 SB6.1)
ADC_3: Connectors (CN1.A11 TP13.1), Configuration (SB7.1 SB8.1 SB9.1)
ADC_4: Connectors (CN1.B09 TP10.1), Configuration (SB10.1 SB11.1 SB12.1)
ADC_5: Connectors (CN1.B10 TP12.1), Configuration (SB13.1 SB14.1 SB15.1)
ADC_6: Connectors (CN1.B11 TP14.1), Configuration (SB16.1 SB17.1 SB18.1)
M1_ADC_1: Connectors (CN2.A09), Configuration (SB1.2)
M1_ADC_2: Connectors (CN2.A10), Configuration (SB4.2)
M1_ADC_3: Connectors (CN2.A11), Configuration (SB7.2)
M1_ADC_4: Connectors (CN2.B09), Configuration (SB10.2)
M1_ADC_5: Connectors (CN2.B10), Configuration (SB13.2)
M1_ADC_6: Connectors (CN2.B11), Configuration (SB16.2)
M1_SPI1_MISO: Connectors (CN2.B01), Configuration (SB27.2)
M1_SPI1_nSS: Connectors (CN2.A01), Configuration (SB24.2 SB25.2)
M1_SPI2_MISO: Connectors (CN2.B03), Configuration (SB28.2)
M1_SPI2_nSS: Connectors (CN2.A03), Configuration (SB23.2 SB26.2)
M1_SPI_nSS: Connectors (CN1.A77 CN2.A77), Configuration (SB23.1 SB24.1)
M2_ADC_1: Connectors (CN3.A09), Configuration (SB2.2)
M2_ADC_2: Connectors (CN3.A10), Configuration (SB5.2)
M2_ADC_3: Connectors (CN3.A11), Configuration (SB8.2)
M2_ADC_4: Connectors (CN3.B09), Configuration (SB11.2)
M2_ADC_5: Connectors (CN3.B10), Configuration (SB14.2)
M2_ADC_6: Connectors (CN3.B11), Configuration (SB17.2)
M2_SPI1_MISO: Connectors (CN3.B01), Configuration (SB31.2)
M2_SPI1_nSS: Connectors (CN3.A01), Configuration (SB22.2 SB29.2)
M2_SPI2_MISO: Connectors (CN3.B03), Configuration (SB32.2)
M2_SPI2_nSS: Connectors (CN3.A03), Configuration (SB21.2 SB30.2)
M2_SPI_nSS: Connectors (CN1.A79 CN3.A77), Configuration (SB21.1 SB22.1)
M3_ADC_1: Connectors (CN4.A09), Configuration (SB3.2)
M3_ADC_2: Connectors (CN4.A10), Configuration (SB6.2)
M3_ADC_3: Connectors (CN4.A11), Configuration (SB9.2)
M3_ADC_4: Connectors (CN4.B09), Configuration (SB12.2)
M3_ADC_5: Connectors (CN4.B10), Configuration (SB15.2)
M3_ADC_6: Connectors (CN4.B11), Configuration (SB18.2)
M3_SPI1_MISO: Connectors (CN4.B01), Configuration (SB35.2)
M3_SPI1_nSS: Connectors (CN4.A01), Configuration (SB20.2 SB33.2)
M3_SPI2_MISO: Connectors (CN4.B03), Configuration (SB36.2)
M3_SPI2_nSS: Connectors (CN4.A03), Configuration (SB19.2 SB34.2)
M3_SPI_nSS: Connectors (CN1.A81 CN4.A77), Configuration (SB19.1 SB20.1)
SPI1_MISO: Connectors (CN1.B01 TP2.1), Configuration (SB27.1 SB31.1 SB35.1)
SPI1_nSS: Connectors (CN1.A01 TP1.1), Configuration (SB25.1 SB29.1 SB33.1)
SPI2_MISO: Connectors (CN1.B03 TP6.1), Configuration (SB28.1 SB32.1 SB36.1)
SPI2_nSS: Connectors (CN1.A03 TP5.1), Configuration (SB26.1 SB30.1 SB34.1)

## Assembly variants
DEFAULT: not fitted R1 SB2 SB3 SB5 SB6 SB7 SB9 SB10 SB12 SB13 SB14 SB16 SB17 SB19 SB20 SB21 SB22 SB23 SB24 SB29 SB30 SB31 SB32 SB33 SB34 SB35 SB36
